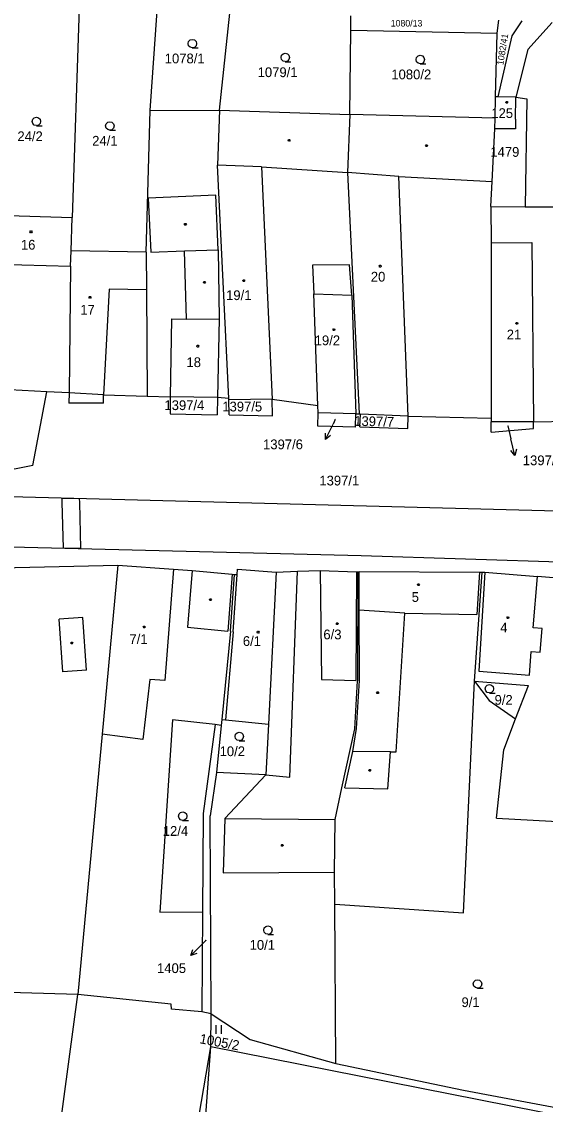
# Model space of a CAD drawing. Extents: x -850689 to -847910, y -1058374 to -1054747.
# Drawn here: x -849516.8 to -849425.6, y -1056444.2 to -1056255.5 of the extents above; entities that cross this region are included whole.
import ezdxf

# ---------------------------------------------------------------- set-up
doc = ezdxf.new("R2010")
doc.units = 0
for name, color, linetype in [('KN_BREMENA', 7, 'Continuous'), ('KN_HRANICE', 7, 'Continuous'), ('KN_KULTURY', 7, 'Continuous'), ('KN_PARCELY', 7, 'Continuous'), ('KN_SLUCKY', 7, 'Continuous'), ('KN_STAVEBNI', 7, 'Continuous')]:
    doc.layers.add(name, color=color, linetype=linetype)

# ---------------------------------------------------------------- blocks, each defined once
blk = doc.blocks.new('304')
blk.add_lwpolyline([(0, 0), (-0.38, 0.1), (-0.65, 0.37), (-0.75, 0.74), (-0.65, 1.11), (-0.38, 1.38), (-0.01, 1.48), (0.36, 1.38), (0.63, 1.11), (0.73, 0.73), (0.63, 0.35), (0.36, 0.08), (-0.02, -0.02), (0.98, -0.02)])
blk = doc.blocks.new('306')
for p, q in [((-0.5, 1.5), (-0.5, 0)), ((0.5, 0), (0.5, 1.5))]:
    blk.add_line(p, q)
blk = doc.blocks.new('10292')
blk.add_line((0, 3), (0, 0))
blk.add_lwpolyline([(-0.5, 2), (0, 3), (0.5, 2)])
blk = doc.blocks.new('402')
blk.add_lwpolyline([(0.09, 0.15), (0.18, 0), (0.09, -0.15), (-0.09, -0.15), (-0.18, 0), (-0.09, 0.15), (0.09, 0.15)])

msp = doc.modelspace()

# ---------------------------------------------------------------- linework, layer by layer
at = {"layer": 'KN_BREMENA'}
msp.add_lwpolyline([(-849509.54, -1056347.25), (-849509.75, -1056339.2), (-849509.77, -1056338.52), (-849506.77, -1056338.6), (-849506.75, -1056339.28), (-849506.54, -1056347.32)], close=True, dxfattribs=at)
at = {"layer": 'KN_HRANICE'}
for p, q in [((-849506.8, -1056253.15), (-849508.04, -1056289.59)), ((-849494.45, -1056270.95), (-849493.22, -1056253.57)), ((-849482.35, -1056270.93), (-849480.53, -1056253.97)), ((-849459.46, -1056256.93), (-849459.44, -1056254.46)), ((-849433.96, -1056257.48), (-849433.67, -1056255.23)), ((-849431.37, -1056257.95), (-849429.59, -1056255.35)), ((-849459.61, -1056271.66), (-849459.46, -1056256.93)), ((-849459.46, -1056256.93), (-849433.96, -1056257.48)), ((-849424.4, -1056255.6), (-849428.61, -1056260.33)), ((-849434.27, -1056268.55), (-849433.96, -1056257.48)), ((-849433.77, -1056268.56), (-849431.37, -1056257.95)), ((-849428.61, -1056260.33), (-849430.72, -1056268.66)), ((-849434.34, -1056272.32), (-849434.27, -1056268.55)), ((-849433.77, -1056268.56), (-849434.27, -1056268.55)), ((-849430.72, -1056268.66), (-849433.77, -1056268.56)), ((-849430.76, -1056272.49), (-849430.72, -1056268.66)), ((-849430.72, -1056268.66), (-849428.8, -1056268.93)), ((-849428.8, -1056268.93), (-849429.11, -1056287.73)), ((-849495.12, -1056295.64), (-849494.45, -1056270.95)), ((-849494.45, -1056270.95), (-849482.35, -1056270.93)), ((-849482.35, -1056270.93), (-849482.67, -1056280.51)), ((-849482.35, -1056270.93), (-849459.61, -1056271.66)), ((-849459.61, -1056271.66), (-849460.03, -1056281.78)), ((-849434.34, -1056272.32), (-849459.61, -1056271.66)), ((-849434.38, -1056274.15), (-849434.34, -1056272.32)), ((-849434.84, -1056283.32), (-849434.38, -1056274.15)), ((-849430.78, -1056274.18), (-849434.38, -1056274.15)), ((-849430.76, -1056272.49), (-849430.78, -1056274.18)), ((-849480.75, -1056321.14), (-849482.67, -1056280.51)), ((-849460.03, -1056281.78), (-849458.02, -1056323.85)), ((-849435.06, -1056287.7), (-849434.84, -1056283.32)), ((-849521, -1056289.21), (-849508.04, -1056289.59)), ((-849435.06, -1056287.7), (-849434.99, -1056294.05)), ((-849435.06, -1056287.7), (-849429.11, -1056287.73)), ((-849429.11, -1056287.73), (-849411.38, -1056287.83)), ((-849508.22, -1056295.39), (-849508.04, -1056289.59)), ((-849434.99, -1056294.05), (-849435.03, -1056324.6)), ((-849508.3, -1056298.1), (-849508.22, -1056295.39)), ((-849495.12, -1056295.64), (-849508.22, -1056295.39)), ((-849495.12, -1056295.64), (-849495.08, -1056302.24)), ((-849508.3, -1056298.1), (-849508.54, -1056320.18)), ((-849459.67, -1056297.88), (-849466.12, -1056297.93)), ((-849466.12, -1056297.93), (-849465.89, -1056302.94)), ((-849459.31, -1056303.12), (-849459.67, -1056297.88)), ((-849495.08, -1056302.24), (-849494.97, -1056320.74)), ((-849465.19, -1056322.38), (-849465.89, -1056302.94)), ((-849459.31, -1056303.12), (-849458.61, -1056323.81)), ((-849512.43, -1056319.98), (-849521.32, -1056319.52)), ((-849514.89, -1056332.85), (-849512.43, -1056319.98)), ((-849508.54, -1056320.18), (-849512.43, -1056319.98)), ((-849508.54, -1056320.18), (-849508.59, -1056321.95)), ((-849502.57, -1056321.97), (-849502.53, -1056320.49)), ((-849502.53, -1056320.49), (-849494.97, -1056320.74)), ((-849494.97, -1056320.74), (-849490.92, -1056320.87)), ((-849490.92, -1056320.87), (-849490.97, -1056323.82)), ((-849482.68, -1056320.99), (-849490.92, -1056320.87)), ((-849482.68, -1056320.99), (-849482.75, -1056323.99)), ((-849480.75, -1056321.14), (-849482.68, -1056320.99)), ((-849480.74, -1056321.39), (-849480.75, -1056321.14)), ((-849473.17, -1056321.25), (-849480.74, -1056321.39)), ((-849480.64, -1056323.99), (-849480.74, -1056321.39)), ((-849473.12, -1056324.15), (-849473.17, -1056321.25)), ((-849473.17, -1056321.25), (-849465.19, -1056322.38)), ((-849502.57, -1056321.97), (-849508.59, -1056321.95)), ((-849465.18, -1056323.63), (-849465.19, -1056322.38)), ((-849490.97, -1056323.82), (-849482.75, -1056323.99)), ((-849480.64, -1056323.99), (-849473.12, -1056324.15)), ((-849465.24, -1056325.98), (-849465.18, -1056323.63)), ((-849458.61, -1056323.81), (-849465.18, -1056323.63)), ((-849458.67, -1056326.16), (-849458.61, -1056323.81)), ((-849458.61, -1056323.81), (-849458.02, -1056323.85)), ((-849458.02, -1056323.85), (-849457.77, -1056323.86)), ((-849457.87, -1056326.11), (-849457.77, -1056323.86)), ((-849449.46, -1056324.22), (-849457.77, -1056323.86)), ((-849449.55, -1056326.37), (-849449.46, -1056324.22)), ((-849449.46, -1056324.22), (-849435.03, -1056324.6)), ((-849435.03, -1056324.6), (-849435.03, -1056325.25)), ((-849427.65, -1056325.24), (-849414.63, -1056324.97)), ((-849458.67, -1056326.16), (-849465.24, -1056325.98)), ((-849457.87, -1056326.11), (-849449.55, -1056326.37)), ((-849427.65, -1056325.24), (-849435.03, -1056325.25)), ((-849435.03, -1056327.05), (-849435.03, -1056325.25)), ((-849435.03, -1056327.05), (-849427.65, -1056326.39)), ((-849427.65, -1056326.39), (-849427.65, -1056325.24)), ((-849514.89, -1056332.85), (-849521.3, -1056334.07)), ((-849406.11, -1056341.28), (-849532.06, -1056337.93)), ((-849534.81, -1056346.62), (-849457.69, -1056348.54)), ((-849457.69, -1056348.54), (-849398.2, -1056350.42)), ((-849520.48, -1056350.65), (-849500.05, -1056350.21)), ((-849500.05, -1056350.21), (-849502.8, -1056379.68)), ((-849500.05, -1056350.21), (-849490.37, -1056350.9)), ((-849490.37, -1056350.9), (-849487.09, -1056351.14)), ((-849487.09, -1056351.14), (-849480.14, -1056351.77)), ((-849479.29, -1056351.85), (-849479.23, -1056350.91)), ((-849479.23, -1056350.91), (-849472.47, -1056351.4)), ((-849472.47, -1056351.4), (-849468.75, -1056351.27)), ((-849470.08, -1056387.16), (-849468.75, -1056351.27)), ((-849468.75, -1056351.27), (-849464.83, -1056351.13)), ((-849464.83, -1056351.13), (-849458.48, -1056351.34)), ((-849458.48, -1056351.34), (-849458.24, -1056351.35)), ((-849458.24, -1056351.35), (-849458.31, -1056370.39)), ((-849458.24, -1056351.35), (-849457.99, -1056351.31)), ((-849457.99, -1056351.31), (-849437.06, -1056351.45)), ((-849437.9, -1056370.41), (-849436.56, -1056351.44)), ((-849437.06, -1056351.45), (-849436.56, -1056351.44)), ((-849436.56, -1056351.44), (-849436.13, -1056351.44)), ((-849436.13, -1056351.44), (-849426.94, -1056352.2)), ((-849480.43, -1056361.68), (-849479.72, -1056351.81)), ((-849480.14, -1056351.77), (-849479.72, -1056351.81)), ((-849479.72, -1056351.81), (-849479.29, -1056351.85)), ((-849416.15, -1056353.07), (-849426.94, -1056352.2)), ((-849480.43, -1056361.68), (-849481.92, -1056377.09)), ((-849458.76, -1056378.72), (-849458.31, -1056370.39)), ((-849439.86, -1056410.77), (-849437.9, -1056370.41)), ((-849437.9, -1056370.41), (-849428.51, -1056371.18)), ((-849437.9, -1056370.41), (-849435.36, -1056373.81)), ((-849430.75, -1056376.96), (-849428.51, -1056371.18)), ((-849435.36, -1056373.81), (-849430.75, -1056376.96)), ((-849490.51, -1056377.17), (-849492.74, -1056410.69)), ((-849483.12, -1056378), (-849490.51, -1056377.17)), ((-849483.12, -1056378), (-849485.17, -1056393.49)), ((-849482.05, -1056378.12), (-849483.12, -1056378)), ((-849481.92, -1056377.09), (-849482.05, -1056378.12)), ((-849481.92, -1056377.09), (-849481.33, -1056377.15)), ((-849481.33, -1056377.15), (-849473.83, -1056377.89)), ((-849473.83, -1056377.89), (-849474.29, -1056386.75)), ((-849432.79, -1056382.39), (-849430.75, -1056376.96)), ((-849502.8, -1056379.68), (-849507.03, -1056425.02)), ((-849482.05, -1056378.12), (-849482.89, -1056386.33)), ((-849461.04, -1056389.01), (-849458.76, -1056378.72)), ((-849434.1, -1056394.27), (-849432.79, -1056382.39)), ((-849482.89, -1056386.33), (-849483.96, -1056393.89)), ((-849474.29, -1056386.75), (-849482.89, -1056386.33)), ((-849474.29, -1056386.75), (-849481.42, -1056394.34)), ((-849474.29, -1056386.75), (-849470.08, -1056387.16)), ((-849462.21, -1056394.54), (-849461.04, -1056389.01)), ((-849485.17, -1056393.49), (-849485.33, -1056410.62)), ((-849483.82, -1056428.39), (-849483.96, -1056393.89)), ((-849481.42, -1056394.34), (-849481.68, -1056403.84)), ((-849462.29, -1056403.7), (-849462.21, -1056394.54)), ((-849434.1, -1056394.27), (-849418.85, -1056395.14)), ((-849481.68, -1056403.84), (-849462.29, -1056403.7)), ((-849462.25, -1056409.27), (-849462.29, -1056403.7)), ((-849462.06, -1056437.04), (-849462.25, -1056409.27)), ((-849462.25, -1056409.27), (-849439.86, -1056410.77)), ((-849492.74, -1056410.69), (-849485.33, -1056410.62)), ((-849485.33, -1056410.62), (-849485.43, -1056428.03)), ((-849507.03, -1056425.02), (-849531.06, -1056424.37)), ((-849512.05, -1056462.5), (-849507.03, -1056425.02)), ((-849490.78, -1056426.73), (-849507.03, -1056425.02)), ((-849490.69, -1056427.59), (-849490.78, -1056426.73)), ((-849485.43, -1056428.03), (-849490.69, -1056427.59)), ((-849483.82, -1056428.39), (-849485.43, -1056428.03)), ((-849483.86, -1056434.18), (-849483.82, -1056428.39)), ((-849483.82, -1056428.39), (-849476.99, -1056432.86)), ((-849489.06, -1056464.49), (-849483.86, -1056434.18)), ((-849486.28, -1056467.61), (-849483.86, -1056434.18)), ((-849371.72, -1056456.31), (-849483.86, -1056434.18)), ((-849476.99, -1056432.86), (-849462.06, -1056437.04)), ((-849462.06, -1056437.04), (-849439.82, -1056441.73)), ((-849439.82, -1056441.73), (-849419.09, -1056445.59))]:
    msp.add_line(p, q, dxfattribs=at)
at = {"layer": 'KN_PARCELY'}
for p, q in [((-849462.18, -1056324.8), (-849462.57, -1056325.6)), ((-849432.09, -1056325.94), (-849431.57, -1056328.16)), ((-849484.68, -1056415.57), (-849485.24, -1056416.13))]:
    msp.add_line(p, q, dxfattribs=at)
at = {"layer": 'KN_SLUCKY'}
for p, q in [((-849475.02, -1056280.76), (-849482.67, -1056280.51)), ((-849475.02, -1056280.76), (-849460.03, -1056281.78)), ((-849475.02, -1056280.76), (-849473.17, -1056321.25)), ((-849451.09, -1056282.46), (-849460.03, -1056281.78)), ((-849449.46, -1056324.22), (-849451.09, -1056282.46)), ((-849451.09, -1056282.46), (-849434.84, -1056283.32)), ((-849482.97, -1056285.71), (-849494.77, -1056286.24)), ((-849494.77, -1056286.24), (-849494.34, -1056295.65)), ((-849482.56, -1056295.24), (-849482.97, -1056285.71)), ((-849434.99, -1056294.05), (-849427.93, -1056293.99)), ((-849427.93, -1056293.99), (-849427.65, -1056325.24)), ((-849494.34, -1056295.65), (-849488.42, -1056295.39)), ((-849488.42, -1056295.39), (-849482.56, -1056295.24)), ((-849488.1, -1056307.35), (-849488.42, -1056295.39)), ((-849482.56, -1056295.24), (-849482.38, -1056307.29)), ((-849521.24, -1056297.73), (-849508.3, -1056298.1)), ((-849501.58, -1056302.08), (-849502.53, -1056320.49)), ((-849495.08, -1056302.24), (-849501.58, -1056302.08)), ((-849465.89, -1056302.94), (-849459.31, -1056303.12)), ((-849490.71, -1056307.29), (-849490.92, -1056320.87)), ((-849490.71, -1056307.29), (-849488.1, -1056307.35)), ((-849488.1, -1056307.35), (-849482.38, -1056307.29)), ((-849482.38, -1056307.29), (-849482.68, -1056320.99)), ((-849502.53, -1056320.49), (-849508.54, -1056320.18)), ((-849490.37, -1056350.9), (-849491.86, -1056370.31)), ((-849487.09, -1056351.14), (-849487.95, -1056360.98)), ((-849472.47, -1056351.4), (-849473.83, -1056377.89)), ((-849464.83, -1056351.13), (-849464.57, -1056370.11)), ((-849458.48, -1056351.34), (-849458.6, -1056370.29)), ((-849457.99, -1056358.05), (-849457.99, -1056351.31)), ((-849437.06, -1056351.45), (-849437.53, -1056358.8)), ((-849436.13, -1056351.44), (-849437.16, -1056368.68)), ((-849480.14, -1056351.77), (-849480.9, -1056361.73)), ((-849479.96, -1056361.85), (-849479.29, -1056351.85)), ((-849427.67, -1056361.1), (-849426.94, -1056352.2)), ((-849450.04, -1056358.54), (-849457.99, -1056358.05)), ((-849457.98, -1056370.31), (-849457.99, -1056358.05)), ((-849451.58, -1056382.74), (-849450.04, -1056358.54)), ((-849450.04, -1056358.54), (-849437.53, -1056358.8)), ((-849506.16, -1056359.3), (-849510.3, -1056359.6)), ((-849509.64, -1056368.77), (-849510.3, -1056359.6)), ((-849505.5, -1056368.48), (-849506.16, -1056359.3)), ((-849487.95, -1056360.98), (-849480.9, -1056361.73)), ((-849479.96, -1056361.85), (-849481.33, -1056377.15)), ((-849426.11, -1056361.23), (-849427.67, -1056361.1)), ((-849426.45, -1056365.39), (-849426.11, -1056361.23)), ((-849428.33, -1056369.36), (-849428.02, -1056365.27)), ((-849428.02, -1056365.27), (-849426.45, -1056365.39)), ((-849505.5, -1056368.48), (-849509.64, -1056368.77)), ((-849494.48, -1056370.13), (-849495.68, -1056380.57)), ((-849491.86, -1056370.31), (-849494.48, -1056370.13)), ((-849464.57, -1056370.11), (-849458.6, -1056370.29)), ((-849458.45, -1056378.68), (-849457.98, -1056370.31)), ((-849437.16, -1056368.68), (-849428.33, -1056369.36)), ((-849495.68, -1056380.57), (-849502.8, -1056379.68)), ((-849459.13, -1056382.68), (-849458.45, -1056378.68)), ((-849460.5, -1056389.02), (-849459.13, -1056382.68)), ((-849452.58, -1056382.72), (-849459.13, -1056382.68)), ((-849453, -1056389.21), (-849452.58, -1056382.72)), ((-849452.58, -1056382.72), (-849451.58, -1056382.74)), ((-849460.5, -1056389.02), (-849453, -1056389.21)), ((-849481.42, -1056394.34), (-849462.21, -1056394.54))]:
    msp.add_line(p, q, dxfattribs=at)
at = {"layer": 'KN_STAVEBNI'}
for p, q in [((-849434.34, -1056272.32), (-849434.27, -1056268.55)), ((-849433.77, -1056268.56), (-849434.27, -1056268.55)), ((-849430.72, -1056268.66), (-849433.77, -1056268.56)), ((-849430.76, -1056272.49), (-849430.72, -1056268.66)), ((-849434.38, -1056274.15), (-849434.34, -1056272.32)), ((-849430.78, -1056274.18), (-849434.38, -1056274.15)), ((-849430.76, -1056272.49), (-849430.78, -1056274.18)), ((-849475.02, -1056280.76), (-849482.67, -1056280.51)), ((-849480.75, -1056321.14), (-849482.67, -1056280.51)), ((-849475.02, -1056280.76), (-849473.17, -1056321.25)), ((-849451.09, -1056282.46), (-849460.03, -1056281.78)), ((-849460.03, -1056281.78), (-849458.02, -1056323.85)), ((-849449.46, -1056324.22), (-849451.09, -1056282.46)), ((-849521, -1056289.21), (-849508.04, -1056289.59)), ((-849508.22, -1056295.39), (-849508.04, -1056289.59)), ((-849434.99, -1056294.05), (-849435.03, -1056324.6)), ((-849434.99, -1056294.05), (-849427.93, -1056293.99)), ((-849427.93, -1056293.99), (-849427.65, -1056325.24)), ((-849508.3, -1056298.1), (-849508.22, -1056295.39)), ((-849508.3, -1056298.1), (-849508.22, -1056295.39)), ((-849495.12, -1056295.64), (-849508.22, -1056295.39)), ((-849495.12, -1056295.64), (-849495.08, -1056302.24)), ((-849521.24, -1056297.73), (-849508.3, -1056298.1)), ((-849508.3, -1056298.1), (-849508.54, -1056320.18)), ((-849501.58, -1056302.08), (-849502.53, -1056320.49)), ((-849495.08, -1056302.24), (-849501.58, -1056302.08)), ((-849465.89, -1056302.94), (-849459.31, -1056303.12)), ((-849465.19, -1056322.38), (-849465.89, -1056302.94)), ((-849459.31, -1056303.12), (-849458.61, -1056323.81)), ((-849490.71, -1056307.29), (-849490.92, -1056320.87)), ((-849490.71, -1056307.29), (-849488.1, -1056307.35)), ((-849488.1, -1056307.35), (-849482.38, -1056307.29)), ((-849482.38, -1056307.29), (-849482.68, -1056320.99)), ((-849502.53, -1056320.49), (-849508.54, -1056320.18)), ((-849482.68, -1056320.99), (-849490.92, -1056320.87)), ((-849480.74, -1056321.39), (-849480.75, -1056321.14)), ((-849473.17, -1056321.25), (-849480.74, -1056321.39)), ((-849465.18, -1056323.63), (-849465.19, -1056322.38)), ((-849458.61, -1056323.81), (-849465.18, -1056323.63)), ((-849458.02, -1056323.85), (-849457.77, -1056323.86)), ((-849449.46, -1056324.22), (-849457.77, -1056323.86)), ((-849435.03, -1056324.6), (-849435.03, -1056325.25)), ((-849427.65, -1056325.24), (-849435.03, -1056325.25)), ((-849500.05, -1056350.21), (-849502.8, -1056379.68)), ((-849500.05, -1056350.21), (-849490.37, -1056350.9)), ((-849490.37, -1056350.9), (-849491.86, -1056370.31)), ((-849479.29, -1056351.85), (-849479.23, -1056350.91)), ((-849479.23, -1056350.91), (-849472.47, -1056351.4)), ((-849472.47, -1056351.4), (-849473.83, -1056377.89)), ((-849464.83, -1056351.13), (-849458.48, -1056351.34)), ((-849464.83, -1056351.13), (-849464.57, -1056370.11)), ((-849458.48, -1056351.34), (-849458.6, -1056370.29)), ((-849457.99, -1056358.05), (-849457.99, -1056351.31)), ((-849457.99, -1056351.31), (-849437.06, -1056351.45)), ((-849437.06, -1056351.45), (-849437.53, -1056358.8)), ((-849436.13, -1056351.44), (-849437.16, -1056368.68)), ((-849436.13, -1056351.44), (-849426.94, -1056352.2)), ((-849479.96, -1056361.85), (-849479.29, -1056351.85)), ((-849427.67, -1056361.1), (-849426.94, -1056352.2)), ((-849450.04, -1056358.54), (-849457.99, -1056358.05)), ((-849450.04, -1056358.54), (-849437.53, -1056358.8)), ((-849479.96, -1056361.85), (-849481.33, -1056377.15)), ((-849426.11, -1056361.23), (-849427.67, -1056361.1)), ((-849426.45, -1056365.39), (-849426.11, -1056361.23)), ((-849428.33, -1056369.36), (-849428.02, -1056365.27)), ((-849428.02, -1056365.27), (-849426.45, -1056365.39)), ((-849494.48, -1056370.13), (-849495.68, -1056380.57)), ((-849491.86, -1056370.31), (-849494.48, -1056370.13)), ((-849464.57, -1056370.11), (-849458.6, -1056370.29)), ((-849437.16, -1056368.68), (-849428.33, -1056369.36)), ((-849481.33, -1056377.15), (-849473.83, -1056377.89)), ((-849495.68, -1056380.57), (-849502.8, -1056379.68))]:
    msp.add_line(p, q, dxfattribs=at)

# ---------------------------------------------------------------- block references
at = {"layer": 'KN_KULTURY'}
for name, p in [('304', (-849487.07, -1056260.04)), ('304', (-849470.88, -1056262.44)), ('304', (-849447.35, -1056262.82)), ('402', (-849432.3, -1056269.56)), ('304', (-849514.24, -1056273.6)), ('304', (-849501.45, -1056274.39)), ('402', (-849470.23, -1056276.14)), ('402', (-849446.26, -1056277.09)), ('402', (-849488.3, -1056290.81)), ('402', (-849515.19, -1056292.11)), ('402', (-849454.34, -1056298.09)), ('402', (-849478.12, -1056300.63)), ('402', (-849484.97, -1056300.89)), ('402', (-849504.91, -1056303.51)), ('402', (-849430.54, -1056308.07)), ('402', (-849462.42, -1056309.16)), ('402', (-849486.13, -1056312.03)), ('402', (-849447.68, -1056353.59)), ('402', (-849483.92, -1056356.22)), ('402', (-849495.46, -1056360.98)), ('402', (-849461.83, -1056360.39)), ('402', (-849432.09, -1056359.36)), ('402', (-849475.63, -1056361.88)), ('402', (-849508.08, -1056363.77)), ('402', (-849454.79, -1056372.42)), ('304', (-849435.31, -1056372.47)), ('304', (-849478.89, -1056380.79)), ('402', (-849456.17, -1056385.97)), ('304', (-849488.75, -1056394.68)), ('402', (-849471.42, -1056399.02)), ('304', (-849473.9, -1056414.54)), ('304', (-849437.38, -1056423.93)), ('306', (-849482.51, -1056431.87))]:
    msp.add_blockref(name, p, dxfattribs=at)
at = {"layer": 'KN_PARCELY'}
for p, rotation in [((-849462.57, -1056325.6), 153.95376000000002), ((-849431.57, -1056328.16), -166.85592700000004), ((-849485.24, -1056416.13), 134.988857)]:
    msp.add_blockref('10292', p, dxfattribs=dict(at, rotation=rotation))

# ---------------------------------------------------------------- texts
for s, height, p in [('1080/13', 1.14, (-849452.51, -1056256.32)), ('1078/1', 1.7, (-849491.89, -1056262.74)), ('1079/1', 1.7, (-849475.7, -1056265.14)), ('1080/2', 1.7, (-849452.41, -1056265.52)), ('125', 1.7, (-849434.99, -1056272.27)), ('24/2', 1.7, (-849517.56, -1056276.3)), ('24/1', 1.7, (-849504.53, -1056277.09)), ('1479', 1.7, (-849435.16, -1056279.03)), ('16', 1.7, (-849516.95, -1056295.21)), ('20', 1.7, (-849455.98, -1056300.78)), ('19/1', 1.7, (-849481.2, -1056304)), ('17', 1.7, (-849506.6, -1056306.53)), ('21', 1.7, (-849432.3, -1056310.85)), ('19/2', 1.7, (-849465.76, -1056311.87)), ('18', 1.7, (-849488.1, -1056315.68)), ('1397/4', 1.7, (-849491.94, -1056323.17)), ('1397/5', 1.7, (-849481.86, -1056323.41)), ('1397/6', 0.1, (-849462.48, -1056324.8)), ('1397/8', 0.1, (-849432.39, -1056325.94)), ('1397/6', 1.7, (-849474.76, -1056330)), ('1397/8', 1.7, (-849429.5, -1056332.78)), ('1397/1', 1.7, (-849464.95, -1056336.31)), ('5', 1.7, (-849448.86, -1056356.6)), ('4', 1.7, (-849433.43, -1056361.92)), ('7/1', 1.7, (-849498.04, -1056363.94)), ('6/1', 1.7, (-849478.28, -1056364.28)), ('6/3', 1.7, (-849464.25, -1056363.13)), ('9/2', 1.7, (-849434.42, -1056374.53)), ('10/2', 1.7, (-849482.33, -1056383.49)), ('12/4', 1.7, (-849492.23, -1056397.38)), ('1405', 0.1, (-849484.88, -1056415.57)), ('10/1', 1.7, (-849477.1, -1056417.24)), ('1405', 1.7, (-849493.23, -1056421.29)), ('9/1', 1.7, (-849440.18, -1056427.22))]:
    msp.add_text(s, height=height, dxfattribs=at).set_placement(p)
for s, height, rotation, p in [('1082/41', 1.14, 80.73, (-849432.91, -1056263.11)), ('1397/7', 1.7, 358.614, (-849458.89, -1056325.91)), ('1005/2', 1.7, 349.504, (-849485.91, -1056433.51))]:
    msp.add_text(s, height=height, rotation=rotation, dxfattribs=at).set_placement(p)

doc.saveas('drawing.dxf')
